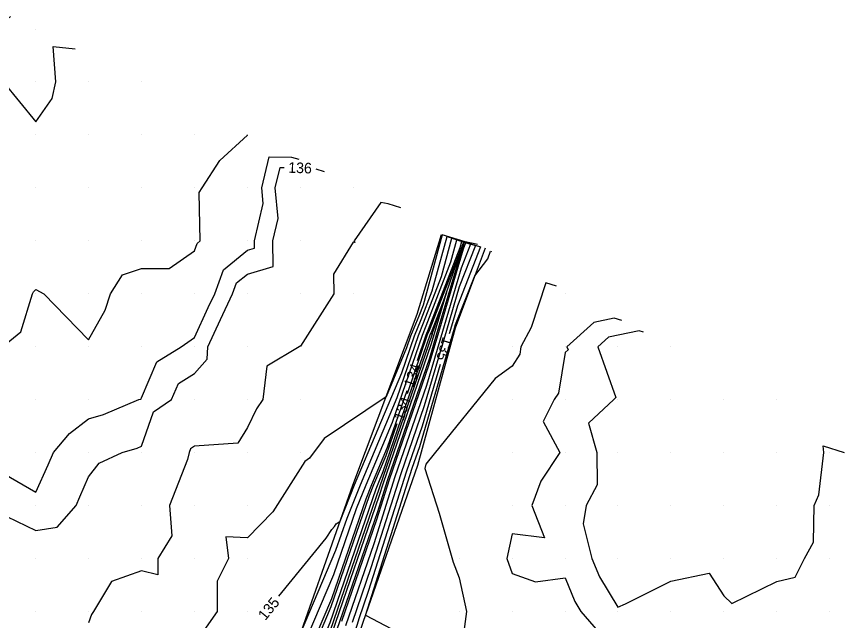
# Model space of a CAD drawing. Extents: x 2354170 to 2357230, y 866100 to 868290.
# Drawn here: x 2354596.3 to 2354751.6, y 867938.3 to 868052.4 of the extents above; entities that cross this region are included whole.
import ezdxf

# ---------------------------------------------------------------- set-up
doc = ezdxf.new("R2010")
doc.units = 0
for name, color, linetype in [('Default', 7, 'Continuous'), ('DTM Contours Major', 7, 'Continuous'), ('DTM Contours Major Text', 7, 'Continuous'), ('DTM Contours Minor', 7, 'Continuous'), ('DTM Contours Minor Text', 7, 'Continuous'), ('Exist DTM QL2 LIDAR Elevation Point', 7, 'Continuous'), ('PH Exist DTM Breakline', 7, 'Continuous')]:
    doc.layers.add(name, color=color, linetype=linetype)

msp = doc.modelspace()

# ---------------------------------------------------------------- linework, layer by layer
at = {"layer": 'Default'}
for points in [[(2354595.22, 868052.4), (2354592.42, 868050.02), (2354592.05, 868047.94), (2354593.85, 868040.02), (2354599.97, 868032.51), (2354603.06, 868036.93), (2354603.79, 868040.02), (2354603.29, 868046.69), (2354607.45, 868046.28)], [(2354593.72, 867990.02), (2354597.18, 867992.8), (2354599.35, 868000.02), (2354599.58, 868000.41), (2354599.97, 868000.81), (2354601.53, 868000.02), (2354609.97, 867991.32), (2354613.08, 867996.91), (2354614.09, 868000.02), (2354616.4, 868003.59), (2354619.97, 868004.77), (2354625.17, 868004.82), (2354629.97, 868008.13), (2354630.46, 868009.52), (2354631.07, 868010.02), (2354630.85, 868019.14), (2354631.4, 868020.02), (2354634.77, 868025.22), (2354639.97, 868029.95), (2354639.98, 868030.01), (2354639.99, 868030.01), (2354640, 868030.01)], [(2354592.64, 867958.82), (2354599.97, 867955.29), (2354604.04, 867955.95), (2354607.59, 867960.02), (2354608.33, 867961.65), (2354609.97, 867965.44), (2354611.96, 867968.02), (2354616.28, 867970.02), (2354619.11, 867970.87), (2354619.97, 867971.23), (2354622.24, 867977.74), (2354625.64, 867980.02), (2354626.92, 867983.07), (2354629.97, 867984.96), (2354632.34, 867987.65), (2354632.51, 867990.02), (2354634.86, 867995.13), (2354637.18, 868000.02), (2354637.92, 868002.07), (2354639.97, 868003.75), (2354644.84, 868005.15), (2354644.79, 868010.02), (2354645.77, 868014.22), (2354645.22, 868020.02), (2354646.14, 868023.85), (2354646.92, 868023.84)], [(2354652.9, 868023.63), (2354654.47, 868023.11)], [(2354668.95, 868016.22), (2354666.58, 868017), (2354665.15, 868017.28), (2354660.13, 868010.03), (2354660.24, 868009.71), (2354659.97, 868009.74), (2354656.26, 868003.73), (2354656.31, 868000.02), (2354649.97, 867990.14), (2354649.89, 867990.1), (2354649.74, 867990.02), (2354643.65, 867986.34), (2354642.91, 867980.02), (2354641.71, 867978.27), (2354639.97, 867974.76), (2354638.18, 867971.8), (2354629.97, 867971.24), (2354629.24, 867970.75), (2354628.98, 867970.02), (2354628.66, 867968.72), (2354625.23, 867960.02), (2354625.67, 867954.32), (2354623.04, 867950.02), (2354623.06, 867946.93), (2354619.97, 867947.68), (2354614.3, 867945.69), (2354610.91, 867940.02), (2354610.54, 867939.45), (2354609.97, 867937.88)], [(2354683.42, 868009.33), (2354683.21, 868009.4), (2354681.13, 868009.8), (2354676.74, 868011.16), (2354673.14, 867997.87), (2354672.32, 867995.77), (2354670.79, 867992), (2354670.04, 867989.8), (2354666.16, 867980.58), (2354654.47, 867972.68), (2354651.72, 867968.94), (2354650.83, 867968.31), (2354644.79, 867958.86), (2354639.97, 867953.89), (2354635.86, 867954.13), (2354636.42, 867950.02), (2354634.25, 867945.74), (2354634.27, 867940.02), (2354629.97, 867933.91)], [(2354645.89, 867942.89), (2354654.83, 867953.84), (2354655.89, 867955.5), (2354656.43, 867956.06), (2354656.74, 867956.55), (2354657.47, 867957.06), (2354660.22, 867963.9), (2354669.14, 867985.11), (2354671.53, 867992.07), (2354672.79, 867995.16), (2354674.9, 868000.59), (2354677.68, 868010.84), (2354684.01, 868008.88), (2354679.63, 867997.75), (2354678.31, 867993.29), (2354678.06, 867992.44)], [(2354648.75, 867929.21), (2354656.31, 867947.01), (2354660.59, 867959.47), (2354662.4, 867963.96), (2354667.35, 867975.74), (2354673.02, 867992.22), (2354673.72, 867993.94), (2354678.42, 868006.02), (2354679.55, 868010.19), (2354682.13, 868009.4), (2354680.35, 868004.86), (2354676.79, 867992.9), (2354673.81, 867982.72), (2354667.84, 867965.42), (2354663.83, 867952.79), (2354658.48, 867937.3)], [(2354650.01, 867935.85), (2354656.7, 867951.59), (2354658.78, 867957.64), (2354661.31, 867963.93), (2354668.25, 867980.42), (2354672.28, 867992.15), (2354673.25, 867994.55), (2354676.66, 868003.3), (2354678.61, 868010.51), (2354683.07, 868009.14), (2354679.99, 868001.3), (2354677.55, 867993.1), (2354673.38, 867978.87), (2354668.93, 867965.98), (2354663.31, 867948.28), (2354659.74, 867937.95)], [(2354672.09, 867987.43), (2354673.76, 867992.29), (2354674.18, 867993.33), (2354680.18, 868008.74), (2354680.49, 868009.87), (2354681.19, 868009.65), (2354680.71, 868008.42), (2354676.04, 867992.7), (2354674.24, 867986.58), (2354666.75, 867964.87), (2354664.34, 867957.3), (2354657.73, 867938.12)], [(2354673.38, 867933.43), (2354662.31, 867939.22), (2354662.25, 867939.19), (2354662.27, 867939.26), (2354662.27, 867939.27), (2354671.11, 867967.08), (2354672.52, 867971.17), (2354679.07, 867993.49), (2354679.28, 867994.19), (2354682.9, 868003.41), (2354685.41, 868006.61), (2354685.88, 868008.06), (2354686.07, 868008)], [(2354698.38, 868001.47), (2354696.33, 868002.1), (2354693.59, 867993.64), (2354691.64, 867990.02), (2354691.41, 867988.58), (2354689.97, 867986.35), (2354686.8, 867984), (2354675.27, 867969.78), (2354673.68, 867967.81), (2354673.49, 867967.01), (2354676.16, 867958.56), (2354678.83, 867949.33), (2354679.97, 867946.34), (2354681.34, 867940.02), (2354680.06, 867930.11)], [(2354677.57, 868000.22), (2354674.65, 867992.72), (2354674.51, 867992.37), (2354665.56, 867966.37), (2354664.58, 867964.03), (2354664.22, 867963.13), (2354655.54, 867937.87), (2354654.07, 867934.43), (2354648.12, 867917.08), (2354648.06, 867916.92), (2354646.55, 867912.63), (2354640.19, 867890.67), (2354648.5, 867914.29), (2354648.64, 867914.7), (2354655.07, 867933.33), (2354655.92, 867935.87), (2354655.95, 867935.99), (2354664.86, 867961.81), (2354665.66, 867964.32), (2354674.67, 867990.43), (2354675.28, 867992.51), (2354677.57, 868000.22)], [(2354710.69, 867994.94), (2354709.25, 867995.38), (2354705.39, 867994.6), (2354700.34, 867990.02), (2354700.54, 867989.45), (2354699.97, 867988.91), (2354698.74, 867981.25), (2354697.94, 867980.02), (2354695.84, 867975.89), (2354698.99, 867970.02), (2354695.38, 867964.61), (2354693.69, 867960.02), (2354696.09, 867953.9), (2354689.97, 867954.66), (2354688.96, 867950.02), (2354689.97, 867947.17), (2354694.37, 867945.62), (2354699.97, 867946.36), (2354701.81, 867941.87), (2354702.95, 867940.02), (2354709.97, 867931.95), (2354713.74, 867930.02), (2354715.23, 867929.3)], [(2354676.37, 867986.68), (2354672.95, 867975.02), (2354670.02, 867966.53), (2354662.79, 867943.78), (2354661.01, 867938.6), (2354660.67, 867937.52), (2354652.69, 867913.72), (2354651.56, 867910.42), (2354650.22, 867906.44), (2354648.52, 867901.59), (2354645.9, 867891.47)], [(2354637.14, 867887.44), (2354638.12, 867890.92), (2354642.81, 867907.13), (2354647.56, 867920.61), (2354647.74, 867921.11), (2354651.41, 867931.82), (2354655.92, 867942.44), (2354662.4, 867961.3), (2354663.49, 867964), (2354666.46, 867971.05), (2354670.14, 867981.76)]]:
    msp.add_lwpolyline(points, dxfattribs=at)
at = {"layer": 'DTM Contours Major'}
for points in [[(2354645.89, 867942.89), (2354654.83, 867953.84), (2354655.89, 867955.5), (2354656.43, 867956.06), (2354656.74, 867956.55), (2354657.47, 867957.06), (2354660.22, 867963.9), (2354669.14, 867985.11), (2354671.53, 867992.07), (2354672.79, 867995.16), (2354674.9, 868000.59), (2354677.68, 868010.84), (2354684.01, 868008.88), (2354679.63, 867997.75), (2354678.31, 867993.29), (2354678.06, 867992.44)], [(2354676.37, 867986.68), (2354672.95, 867975.02), (2354670.02, 867966.53), (2354662.79, 867943.78), (2354661.01, 867938.6), (2354660.67, 867937.52), (2354652.69, 867913.72), (2354651.56, 867910.42), (2354650.22, 867906.44), (2354648.52, 867901.59), (2354645.9, 867891.47)]]:
    msp.add_lwpolyline(points, dxfattribs=at)
at = {"layer": 'DTM Contours Minor'}
for points in [[(2354593.99, 867965.99), (2354599.97, 867962.53), (2354602.31, 867967.68), (2354603.32, 867970.02), (2354606.35, 867973.64), (2354609.97, 867976.41), (2354612.75, 867977.24), (2354619.47, 867980.02), (2354619.85, 867980.14), (2354619.97, 867980.34), (2354622.83, 867987.16), (2354627.46, 867990.02), (2354629.97, 867991.73), (2354632.57, 867997.41), (2354633.82, 868000.02), (2354635.43, 868004.56), (2354639.97, 868008.27), (2354641.33, 868008.66), (2354641.31, 868010.02), (2354642.95, 868017.04), (2354642.67, 868020.02), (2354644.09, 868025.9), (2354648.3, 868025.85), (2354649.65, 868025.41)], [(2354670.18, 867981.18), (2354674.01, 867992.32), (2354674.34, 867993.13), (2354680.77, 868009.64), (2354680.8, 868009.76), (2354680.88, 868009.74), (2354680.83, 868009.61), (2354675.78, 867992.64), (2354674.38, 867987.86), (2354666.39, 867964.69), (2354664.52, 867958.8), (2354656.8, 867936.43), (2354656.71, 867936.15), (2354654.67, 867930.06), (2354649.12, 867913.99), (2354648.79, 867912.98), (2354640.33, 867888.96), (2354639.29, 867884.93), (2354639.09, 867884.15), (2354632.3, 867865.68), (2354631.52, 867863.3), (2354627.46, 867849.02)], [(2354714.79, 867992.77), (2354713.99, 867993.01), (2354708.16, 867991.83), (2354706.17, 867990.02), (2354709.58, 867980.41), (2354709.16, 867980.02), (2354704.43, 867975.56), (2354705.96, 867970.02), (2354706.07, 867963.92), (2354703.96, 867960.02), (2354703.4, 867956.59), (2354705.04, 867950.02), (2354706.47, 867946.53), (2354709.97, 867940.84), (2354711.39, 867941.44), (2354719.97, 867945.74), (2354727.21, 867947.27), (2354729.97, 867942.97), (2354731.45, 867941.5), (2354739.97, 867945.69), (2354743.47, 867946.52), (2354745.23, 867950.02), (2354746.88, 867953.11), (2354747.02, 867960.02), (2354747.94, 867962.05), (2354748.83, 867970.02), (2354748.72, 867971.27), (2354752.69, 867970.02)], [(2354599.07, 867788.9), (2354602.6, 867792.29), (2354603.39, 867793.42), (2354607.53, 867800.54), (2354607.67, 867801.26), (2354609.5, 867805.3), (2354614.47, 867824.86), (2354619.23, 867835.46), (2354620.63, 867838.84), (2354630.89, 867863.59), (2354631.5, 867865.56), (2354636.66, 867883.26), (2354638.39, 867889.41), (2354644.06, 867908.96), (2354647.73, 867919.38), (2354647.86, 867919.77), (2354652.3, 867932.69), (2354655.79, 867940.92), (2354663.01, 867961.91), (2354663.85, 867964.01), (2354666.16, 867969.49), (2354668.23, 867975.51)]]:
    msp.add_lwpolyline(points, dxfattribs=at)
at = {"layer": 'Exist DTM QL2 LIDAR Elevation Point'}
for p, q in [((2354599.97, 868050.02), (2354599.97, 868050.02)), ((2354599.97, 868040.02), (2354599.97, 868040.02)), ((2354609.97, 868040.02), (2354609.97, 868040.02)), ((2354619.97, 868040.02), (2354619.97, 868040.02)), ((2354599.97, 868030.02), (2354599.97, 868030.02)), ((2354609.97, 868030.02), (2354609.97, 868030.02)), ((2354619.97, 868030.02), (2354619.97, 868030.02)), ((2354629.97, 868030.02), (2354629.97, 868030.02)), ((2354639.97, 868030.02), (2354639.97, 868030.02)), ((2354599.97, 868020.02), (2354599.97, 868020.02)), ((2354609.97, 868020.02), (2354609.97, 868020.02)), ((2354619.97, 868020.02), (2354619.97, 868020.02)), ((2354629.97, 868020.02), (2354629.97, 868020.02)), ((2354639.97, 868020.02), (2354639.97, 868020.02)), ((2354649.97, 868020.02), (2354649.97, 868020.02)), ((2354659.97, 868020.02), (2354659.97, 868020.02)), ((2354599.97, 868010.02), (2354599.97, 868010.02)), ((2354609.97, 868010.02), (2354609.97, 868010.02)), ((2354619.97, 868010.02), (2354619.97, 868010.02)), ((2354629.97, 868010.02), (2354629.97, 868010.02)), ((2354639.97, 868010.02), (2354639.97, 868010.02)), ((2354649.97, 868010.02), (2354649.97, 868010.02)), ((2354659.97, 868010.02), (2354659.97, 868010.02)), ((2354599.97, 868000.02), (2354599.97, 868000.02)), ((2354609.97, 868000.02), (2354609.97, 868000.02)), ((2354619.97, 868000.02), (2354619.97, 868000.02)), ((2354629.97, 868000.02), (2354629.97, 868000.02)), ((2354639.97, 868000.02), (2354639.97, 868000.02)), ((2354649.97, 868000.02), (2354649.97, 868000.02)), ((2354659.97, 868000.02), (2354659.97, 868000.02)), ((2354699.97, 868000.02), (2354699.97, 868000.02)), ((2354599.97, 867990.02), (2354599.97, 867990.02)), ((2354609.97, 867990.02), (2354609.97, 867990.02)), ((2354619.97, 867990.02), (2354619.97, 867990.02)), ((2354629.97, 867990.02), (2354629.97, 867990.02)), ((2354639.97, 867990.02), (2354639.97, 867990.02)), ((2354649.97, 867990.02), (2354649.97, 867990.02)), ((2354689.97, 867990.02), (2354689.97, 867990.02)), ((2354699.97, 867990.02), (2354699.97, 867990.02)), ((2354709.97, 867990.02), (2354709.97, 867990.02)), ((2354719.97, 867990.02), (2354719.97, 867990.02)), ((2354599.97, 867980.02), (2354599.97, 867980.02)), ((2354609.97, 867980.02), (2354609.97, 867980.02)), ((2354619.97, 867980.02), (2354619.97, 867980.02)), ((2354629.97, 867980.02), (2354629.97, 867980.02)), ((2354639.97, 867980.02), (2354639.97, 867980.02)), ((2354649.97, 867980.02), (2354649.97, 867980.02)), ((2354689.97, 867980.02), (2354689.97, 867980.02)), ((2354699.97, 867980.02), (2354699.97, 867980.02)), ((2354709.97, 867980.02), (2354709.97, 867980.02)), ((2354719.97, 867980.02), (2354719.97, 867980.02)), ((2354729.97, 867980.02), (2354729.97, 867980.02)), ((2354739.97, 867980.02), (2354739.97, 867980.02)), ((2354599.97, 867970.02), (2354599.97, 867970.02)), ((2354609.97, 867970.02), (2354609.97, 867970.02)), ((2354619.97, 867970.02), (2354619.97, 867970.02)), ((2354629.97, 867970.02), (2354629.97, 867970.02)), ((2354639.97, 867970.02), (2354639.97, 867970.02)), ((2354649.97, 867970.02), (2354649.97, 867970.02)), ((2354689.97, 867970.02), (2354689.97, 867970.02)), ((2354699.97, 867970.02), (2354699.97, 867970.02)), ((2354709.97, 867970.02), (2354709.97, 867970.02)), ((2354719.97, 867970.02), (2354719.97, 867970.02)), ((2354729.97, 867970.02), (2354729.97, 867970.02)), ((2354739.97, 867970.02), (2354739.97, 867970.02)), ((2354749.97, 867970.02), (2354749.97, 867970.02)), ((2354599.97, 867960.02), (2354599.97, 867960.02)), ((2354609.97, 867960.02), (2354609.97, 867960.02)), ((2354619.97, 867960.02), (2354619.97, 867960.02)), ((2354629.97, 867960.02), (2354629.97, 867960.02)), ((2354639.97, 867960.02), (2354639.97, 867960.02)), ((2354689.97, 867960.02), (2354689.97, 867960.02)), ((2354699.97, 867960.02), (2354699.97, 867960.02)), ((2354709.97, 867960.02), (2354709.97, 867960.02)), ((2354719.97, 867960.02), (2354719.97, 867960.02)), ((2354729.97, 867960.02), (2354729.97, 867960.02)), ((2354739.97, 867960.02), (2354739.97, 867960.02)), ((2354749.97, 867960.02), (2354749.97, 867960.02)), ((2354599.97, 867950.02), (2354599.97, 867950.02)), ((2354609.97, 867950.02), (2354609.97, 867950.02)), ((2354619.97, 867950.02), (2354619.97, 867950.02)), ((2354629.97, 867950.02), (2354629.97, 867950.02)), ((2354639.97, 867950.02), (2354639.97, 867950.02)), ((2354679.97, 867950.02), (2354679.97, 867950.02)), ((2354689.97, 867950.02), (2354689.97, 867950.02)), ((2354699.97, 867950.02), (2354699.97, 867950.02)), ((2354709.97, 867950.02), (2354709.97, 867950.02)), ((2354719.97, 867950.02), (2354719.97, 867950.02)), ((2354729.97, 867950.02), (2354729.97, 867950.02)), ((2354739.97, 867950.02), (2354739.97, 867950.02)), ((2354749.97, 867950.02), (2354749.97, 867950.02)), ((2354599.97, 867940.02), (2354599.97, 867940.02)), ((2354609.97, 867940.02), (2354609.97, 867940.02)), ((2354619.97, 867940.02), (2354619.97, 867940.02)), ((2354629.97, 867940.02), (2354629.97, 867940.02)), ((2354639.97, 867940.02), (2354639.97, 867940.02)), ((2354679.97, 867940.02), (2354679.97, 867940.02)), ((2354689.97, 867940.02), (2354689.97, 867940.02)), ((2354699.97, 867940.02), (2354699.97, 867940.02)), ((2354709.97, 867940.02), (2354709.97, 867940.02)), ((2354719.97, 867940.02), (2354719.97, 867940.02)), ((2354729.97, 867940.02), (2354729.97, 867940.02)), ((2354739.97, 867940.02), (2354739.97, 867940.02)), ((2354749.97, 867940.02), (2354749.97, 867940.02))]:
    msp.add_line(p, q, dxfattribs=at)
at = {"layer": 'PH Exist DTM Breakline'}
msp.add_line((2354674.89, 867992.41), (2354680.84, 868009.75), dxfattribs=at)
for points in [[(2354532.21, 867819.08), (2354548.26, 867812.83), (2354562.26, 867807.31), (2354571.58, 867802.92), (2354587.43, 867795.9), (2354596.93, 867792.45), (2354599.12, 867797.03), (2354608.45, 867817.6), (2354619.08, 867841.77), (2354628.1, 867869.88), (2354636.79, 867898.26), (2354647.12, 867927.61), (2354659.87, 867963.89), (2354672.03, 867996.15), (2354676.62, 868011.2)], [(2354684.85, 868008.65), (2354679.21, 867993.53), (2354672.12, 867967.59), (2354661.8, 867937.91), (2354650.59, 867904.79), (2354640.04, 867872.48), (2354627.56, 867840.84), (2354616.77, 867807.35), (2354611.91, 867786.62), (2354609.22, 867782.69), (2354606.65, 867780.73)], [(2354674.89, 867992.41), (2354648.3, 867915.2), (2354631.77, 867865.22), (2354619.33, 867830.72), (2354609.43, 867801.34), (2354604.8, 867792.23), (2354601.68, 867784.58)]]:
    msp.add_lwpolyline(points, dxfattribs=at)

# ---------------------------------------------------------------- texts
at = {"layer": 'Default'}
for s, rotation, p in [('136', 358.0338, (2354647.65, 868022.88)), ('135', 253.6527, (2354676.89, 867991.99)), ('134', 71.0195, (2354671.33, 867982.15)), ('135', 50.7673, (2354643.35, 867938.19))]:
    msp.add_text(s, height=2, rotation=rotation, dxfattribs=at).set_placement(p)
at = {"layer": 'DTM Contours Major Text'}
for rotation, p in [(253.6527, (2354676.89, 867991.99)), (50.7673, (2354643.35, 867938.19))]:
    msp.add_text('135', height=2, rotation=rotation, dxfattribs=at).set_placement(p)
at = {"layer": 'DTM Contours Minor Text'}
msp.add_text('134', height=2, rotation=71.0195, dxfattribs=at).set_placement((2354669.42, 867975.9))

doc.saveas('drawing.dxf')
